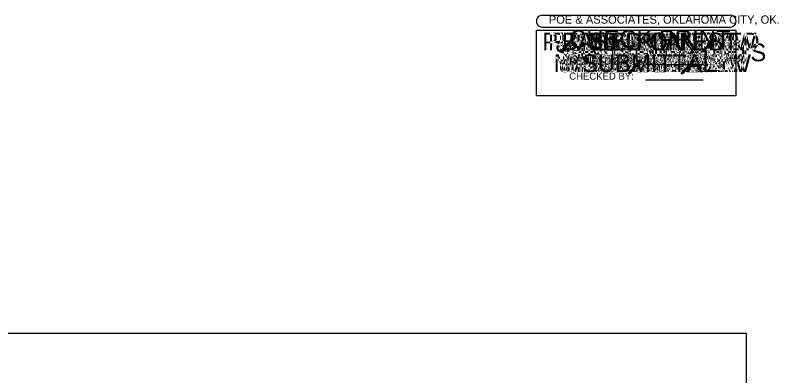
# Model space of a CAD drawing. Extents: x -98.3 to -54.8, y -26.7 to 2.7.
# Drawn here: x -74.57 to -61.71, y -3.42 to 2.66 of the extents above; entities that cross this region are included whole.
import ezdxf

# ---------------------------------------------------------------- set-up
doc = ezdxf.new("R2010")
doc.units = 0
for name, color, linetype in [('SHT_Plot_Shape_Full', 7, 'Continuous'), ('SHT_Stamp_30_Submit', 7, 'Continuous'), ('SHT_Stamp_60_Submit', 7, 'Continuous'), ('SHT_Stamp_70_Submit', 7, 'Continuous'), ('SHT_Stamp_Check_Print', 7, 'Continuous'), ('SHT_Stamp_Est_Inf', 7, 'Continuous'), ('SHT_Stamp_FFR', 7, 'Continuous'), ('SHT_Stamp_Info_Material', 7, 'Continuous'), ('SHT_Stamp_No_Const', 7, 'Continuous'), ('SHT_Stamp_No_Design', 7, 'Continuous'), ('SHT_Stamp_Plan_Hand', 7, 'Continuous'), ('SHT_Stamp_Pre_Plan', 7, 'Continuous'), ('SHT_Stamp_Prop_RW', 7, 'Continuous'), ('SHT_Stamp_Ret_Sub', 7, 'Continuous'), ('SHT_Stamp_Rev_Prop_RW', 7, 'Continuous'), ('SHT_Stamp_Rev_Sheet', 7, 'Continuous'), ('SHT_Stamp_RW_Utilities_Meeting', 7, 'Continuous'), ('SHT_Stamp_RW_Utilities_Review', 7, 'Continuous'), ('SHT_Stamp_Send_Comments', 7, 'Continuous')]:
    doc.layers.add(name, color=color, linetype=linetype)

msp = doc.modelspace()

# ---------------------------------------------------------------- linework, layer by layer
at = {"layer": 'SHT_Plot_Shape_Full'}
msp.add_lwpolyline([(-98.262, -2.701), (-62.262, -2.701), (-62.262, -26.701), (-98.262, -26.701)], close=True, dxfattribs=at)
at = {"layer": 'SHT_Stamp_30_Submit'}
for p, q in [((-65.696, 2.658), (-62.53, 2.658)), ((-65.696, 2.458), (-62.53, 2.458)), ((-65.796, 2.408), (-62.43, 2.408)), ((-65.796, 1.309), (-65.796, 2.408)), ((-62.43, 1.309), (-62.43, 2.408)), ((-64.553, 2.07), (-64.398, 2.243)), ((-64.535, 2.07), (-64.38, 2.243)), ((-64.53, 2.07), (-64.375, 2.243)), ((-64.522, 2.07), (-64.367, 2.243)), ((-64.398, 2.243), (-64.367, 2.243)), ((-64.553, 2.07), (-64.522, 2.07)), ((-65.796, 1.309), (-62.43, 1.309))]:
    msp.add_line(p, q, dxfattribs=at)
for centre, start, end in [((-65.696, 2.559), 89.9952, 270), ((-62.53, 2.559), 270, 90.0048)]:
    msp.add_arc(centre, 0.1, start, end, dxfattribs=at)
at = {"layer": 'SHT_Stamp_60_Submit'}
for p, q in [((-65.696, 2.658), (-62.53, 2.658)), ((-65.696, 2.458), (-62.53, 2.458)), ((-65.796, 2.408), (-62.43, 2.408)), ((-65.796, 1.309), (-65.796, 2.408)), ((-62.43, 1.309), (-62.43, 2.408)), ((-64.553, 2.07), (-64.398, 2.243)), ((-64.535, 2.07), (-64.38, 2.243)), ((-64.53, 2.07), (-64.375, 2.243)), ((-64.522, 2.07), (-64.367, 2.243)), ((-64.398, 2.243), (-64.367, 2.243)), ((-64.553, 2.07), (-64.522, 2.07)), ((-65.796, 1.309), (-62.43, 1.309))]:
    msp.add_line(p, q, dxfattribs=at)
for centre, start, end in [((-65.696, 2.559), 89.9952, 270), ((-62.53, 2.559), 270, 90.0048)]:
    msp.add_arc(centre, 0.1, start, end, dxfattribs=at)
at = {"layer": 'SHT_Stamp_70_Submit'}
for p, q in [((-65.696, 2.658), (-62.53, 2.658)), ((-65.696, 2.458), (-62.53, 2.458)), ((-65.796, 2.408), (-62.43, 2.408)), ((-65.796, 1.309), (-65.796, 2.408)), ((-62.43, 1.309), (-62.43, 2.408)), ((-64.553, 2.07), (-64.398, 2.243)), ((-64.535, 2.07), (-64.38, 2.243)), ((-64.53, 2.07), (-64.375, 2.243)), ((-64.522, 2.07), (-64.367, 2.243)), ((-64.398, 2.243), (-64.367, 2.243)), ((-64.553, 2.07), (-64.522, 2.07)), ((-65.796, 1.309), (-62.43, 1.309))]:
    msp.add_line(p, q, dxfattribs=at)
for centre, start, end in [((-65.696, 2.559), 89.9952, 270), ((-62.53, 2.559), 270, 90.0048)]:
    msp.add_arc(centre, 0.1, start, end, dxfattribs=at)
at = {"layer": 'SHT_Stamp_Check_Print'}
for p, q in [((-65.696, 2.658), (-62.53, 2.658)), ((-65.696, 2.458), (-62.53, 2.458)), ((-65.796, 2.408), (-62.43, 2.408)), ((-65.796, 1.309), (-65.796, 2.408)), ((-62.43, 1.309), (-62.43, 2.408)), ((-63.955, 1.827), (-62.984, 1.827)), ((-63.955, 1.571), (-62.984, 1.571)), ((-65.796, 1.309), (-62.43, 1.309))]:
    msp.add_line(p, q, dxfattribs=at)
for centre, start, end in [((-65.696, 2.559), 89.9952, 270), ((-62.53, 2.559), 270, 90.0048)]:
    msp.add_arc(centre, 0.1, start, end, dxfattribs=at)
at = {"layer": 'SHT_Stamp_Est_Inf'}
for p, q in [((-65.696, 2.658), (-62.53, 2.658)), ((-65.696, 2.458), (-62.53, 2.458)), ((-65.796, 2.408), (-62.43, 2.408)), ((-65.796, 1.309), (-65.796, 2.408)), ((-62.43, 1.309), (-62.43, 2.408)), ((-65.796, 1.309), (-62.43, 1.309))]:
    msp.add_line(p, q, dxfattribs=at)
for centre, start, end in [((-65.696, 2.559), 89.9952, 270), ((-62.53, 2.559), 270, 90.0048)]:
    msp.add_arc(centre, 0.1, start, end, dxfattribs=at)
at = {"layer": 'SHT_Stamp_FFR'}
for p, q in [((-65.696, 2.658), (-62.53, 2.658)), ((-65.696, 2.458), (-62.53, 2.458)), ((-65.796, 2.408), (-62.43, 2.408)), ((-65.796, 1.309), (-65.796, 2.408)), ((-62.43, 1.309), (-62.43, 2.408)), ((-65.796, 1.309), (-62.43, 1.309))]:
    msp.add_line(p, q, dxfattribs=at)
for centre, start, end in [((-65.696, 2.559), 89.9952, 270), ((-62.53, 2.559), 270, 90.0048)]:
    msp.add_arc(centre, 0.1, start, end, dxfattribs=at)
at = {"layer": 'SHT_Stamp_Info_Material'}
for p, q in [((-65.696, 2.658), (-62.53, 2.658)), ((-65.696, 2.458), (-62.53, 2.458)), ((-65.796, 2.408), (-62.43, 2.408)), ((-65.796, 1.309), (-65.796, 2.408)), ((-62.43, 1.309), (-62.43, 2.408)), ((-65.796, 1.309), (-62.43, 1.309))]:
    msp.add_line(p, q, dxfattribs=at)
for centre, start, end in [((-65.696, 2.559), 89.9952, 270), ((-62.53, 2.559), 270, 90.0048)]:
    msp.add_arc(centre, 0.1, start, end, dxfattribs=at)
at = {"layer": 'SHT_Stamp_No_Const'}
for p, q in [((-65.696, 2.658), (-62.53, 2.658)), ((-65.696, 2.458), (-62.53, 2.458)), ((-65.796, 2.408), (-62.43, 2.408)), ((-65.796, 1.309), (-65.796, 2.408)), ((-62.43, 1.309), (-62.43, 2.408)), ((-65.796, 1.309), (-62.43, 1.309))]:
    msp.add_line(p, q, dxfattribs=at)
for centre, start, end in [((-65.696, 2.559), 89.9952, 270), ((-62.53, 2.559), 270, 90.0048)]:
    msp.add_arc(centre, 0.1, start, end, dxfattribs=at)
at = {"layer": 'SHT_Stamp_No_Design'}
for p, q in [((-65.696, 2.658), (-62.53, 2.658)), ((-65.696, 2.458), (-62.53, 2.458)), ((-65.796, 2.408), (-62.43, 2.408)), ((-65.796, 1.309), (-65.796, 2.408)), ((-62.43, 1.309), (-62.43, 2.408)), ((-65.796, 1.309), (-62.43, 1.309))]:
    msp.add_line(p, q, dxfattribs=at)
for centre, start, end in [((-65.696, 2.559), 89.9952, 270), ((-62.53, 2.559), 270, 90.0048)]:
    msp.add_arc(centre, 0.1, start, end, dxfattribs=at)
at = {"layer": 'SHT_Stamp_Plan_Hand'}
for p, q in [((-65.696, 2.658), (-62.53, 2.658)), ((-65.696, 2.458), (-62.53, 2.458)), ((-65.796, 2.408), (-62.43, 2.408)), ((-65.796, 1.309), (-65.796, 2.408)), ((-62.43, 1.309), (-62.43, 2.408)), ((-65.796, 1.309), (-62.43, 1.309))]:
    msp.add_line(p, q, dxfattribs=at)
for centre, start, end in [((-65.696, 2.559), 89.9952, 270), ((-62.53, 2.559), 270, 90.0048)]:
    msp.add_arc(centre, 0.1, start, end, dxfattribs=at)
at = {"layer": 'SHT_Stamp_Pre_Plan'}
for p, q in [((-65.696, 2.658), (-62.53, 2.658)), ((-65.696, 2.458), (-62.53, 2.458)), ((-65.796, 2.408), (-62.43, 2.408)), ((-65.796, 1.309), (-65.796, 2.408)), ((-62.43, 1.309), (-62.43, 2.408)), ((-65.796, 1.309), (-62.43, 1.309))]:
    msp.add_line(p, q, dxfattribs=at)
for centre, start, end in [((-65.696, 2.559), 89.9952, 270), ((-62.53, 2.559), 270, 90.0048)]:
    msp.add_arc(centre, 0.1, start, end, dxfattribs=at)
at = {"layer": 'SHT_Stamp_Prop_RW'}
for p, q in [((-65.696, 2.658), (-62.53, 2.658)), ((-65.696, 2.458), (-62.53, 2.458)), ((-65.796, 2.408), (-62.43, 2.408)), ((-65.796, 1.309), (-65.796, 2.408)), ((-62.43, 1.309), (-62.43, 2.408)), ((-64.249, 1.681), (-64.057, 1.894)), ((-64.227, 1.681), (-64.035, 1.894)), ((-64.221, 1.681), (-64.029, 1.894)), ((-64.212, 1.681), (-64.02, 1.894)), ((-64.057, 1.894), (-64.02, 1.894)), ((-64.249, 1.681), (-64.212, 1.681)), ((-65.796, 1.309), (-62.43, 1.309))]:
    msp.add_line(p, q, dxfattribs=at)
for centre, start, end in [((-65.696, 2.559), 89.9952, 270), ((-62.53, 2.559), 270, 90.0048)]:
    msp.add_arc(centre, 0.1, start, end, dxfattribs=at)
at = {"layer": 'SHT_Stamp_Ret_Sub'}
for p, q in [((-65.696, 2.658), (-62.53, 2.658)), ((-65.696, 2.458), (-62.53, 2.458)), ((-65.796, 2.408), (-62.43, 2.408)), ((-65.796, 1.309), (-65.796, 2.408)), ((-62.43, 1.309), (-62.43, 2.408)), ((-65.796, 1.309), (-62.43, 1.309))]:
    msp.add_line(p, q, dxfattribs=at)
for centre, start, end in [((-65.696, 2.559), 89.9952, 270), ((-62.53, 2.559), 270, 90.0048)]:
    msp.add_arc(centre, 0.1, start, end, dxfattribs=at)
at = {"layer": 'SHT_Stamp_Rev_Prop_RW'}
for p, q in [((-65.696, 2.658), (-62.53, 2.658)), ((-65.696, 2.458), (-62.53, 2.458)), ((-65.796, 2.408), (-62.43, 2.408)), ((-65.796, 1.309), (-65.796, 2.408)), ((-62.43, 1.309), (-62.43, 2.408)), ((-63.359, 1.678), (-63.167, 1.891)), ((-63.337, 1.678), (-63.145, 1.891)), ((-63.331, 1.678), (-63.139, 1.891)), ((-63.321, 1.678), (-63.129, 1.891)), ((-63.167, 1.891), (-63.129, 1.891)), ((-63.359, 1.678), (-63.321, 1.678)), ((-65.796, 1.309), (-62.43, 1.309))]:
    msp.add_line(p, q, dxfattribs=at)
for centre, start, end in [((-65.696, 2.559), 89.9952, 270), ((-62.53, 2.559), 270, 90.0048)]:
    msp.add_arc(centre, 0.1, start, end, dxfattribs=at)
at = {"layer": 'SHT_Stamp_Rev_Sheet'}
for p, q in [((-65.696, 2.658), (-62.53, 2.658)), ((-65.696, 2.458), (-62.53, 2.458)), ((-65.796, 2.408), (-62.43, 2.408)), ((-65.796, 1.309), (-65.796, 2.408)), ((-62.43, 1.309), (-62.43, 2.408)), ((-65.796, 1.309), (-62.43, 1.309))]:
    msp.add_line(p, q, dxfattribs=at)
for centre, start, end in [((-65.696, 2.559), 89.9952, 270), ((-62.53, 2.559), 270, 90.0048)]:
    msp.add_arc(centre, 0.1, start, end, dxfattribs=at)
at = {"layer": 'SHT_Stamp_RW_Utilities_Meeting'}
for p, q in [((-65.696, 2.658), (-62.53, 2.658)), ((-65.696, 2.458), (-62.53, 2.458)), ((-65.796, 2.408), (-62.43, 2.408)), ((-65.796, 1.309), (-65.796, 2.408)), ((-62.43, 1.309), (-62.43, 2.408)), ((-65.394, 2.048), (-65.202, 2.261)), ((-65.372, 2.048), (-65.18, 2.261)), ((-65.366, 2.048), (-65.174, 2.261)), ((-65.356, 2.048), (-65.164, 2.261)), ((-65.202, 2.261), (-65.164, 2.261)), ((-65.394, 2.048), (-65.356, 2.048)), ((-65.796, 1.309), (-62.43, 1.309))]:
    msp.add_line(p, q, dxfattribs=at)
for centre, start, end in [((-65.696, 2.559), 89.9952, 270), ((-62.53, 2.559), 270, 90.0048)]:
    msp.add_arc(centre, 0.1, start, end, dxfattribs=at)
at = {"layer": 'SHT_Stamp_RW_Utilities_Review'}
for p, q in [((-65.696, 2.658), (-62.53, 2.658)), ((-65.696, 2.458), (-62.53, 2.458)), ((-65.796, 2.408), (-62.43, 2.408)), ((-65.796, 1.309), (-65.796, 2.408)), ((-62.43, 1.309), (-62.43, 2.408)), ((-63.006, 2.048), (-62.814, 2.261)), ((-62.984, 2.048), (-62.792, 2.261)), ((-62.977, 2.048), (-62.785, 2.261)), ((-62.968, 2.048), (-62.776, 2.261)), ((-62.814, 2.261), (-62.776, 2.261)), ((-63.006, 2.048), (-62.968, 2.048)), ((-65.796, 1.309), (-62.43, 1.309))]:
    msp.add_line(p, q, dxfattribs=at)
for centre, start, end in [((-65.696, 2.559), 89.9952, 270), ((-62.53, 2.559), 270, 90.0048)]:
    msp.add_arc(centre, 0.1, start, end, dxfattribs=at)
at = {"layer": 'SHT_Stamp_Send_Comments'}
for p, q in [((-65.696, 2.658), (-62.53, 2.658)), ((-65.696, 2.458), (-62.53, 2.458)), ((-65.796, 2.408), (-62.43, 2.408)), ((-65.796, 1.309), (-65.796, 2.408)), ((-62.43, 1.309), (-62.43, 2.408)), ((-65.796, 1.309), (-62.43, 1.309))]:
    msp.add_line(p, q, dxfattribs=at)
for centre, start, end in [((-65.696, 2.559), 89.9952, 270), ((-62.53, 2.559), 270, 90.0048)]:
    msp.add_arc(centre, 0.1, start, end, dxfattribs=at)

# ---------------------------------------------------------------- texts
at = {"layer": 'SHT_Stamp_30_Submit'}
for s, height, p in [('POE & ASSOCIATES, OKLAHOMA CITY, OK.', 0.14, (-65.586, 2.516)), ('30   PLAN', 0.3, (-64.894, 2.066)), ('O', 0.153, (-64.587, 2.155)), ('O', 0.153, (-64.436, 2.071)), ('SUBMITTAL', 0.3, (-65.025, 1.7))]:
    msp.add_text(s, height=height, dxfattribs=at).set_placement(p)
at = {"layer": 'SHT_Stamp_60_Submit'}
for s, height, p in [('POE & ASSOCIATES, OKLAHOMA CITY, OK.', 0.14, (-65.586, 2.516)), ('60   PLAN', 0.3, (-64.901, 2.066)), ('O', 0.153, (-64.587, 2.155)), ('O', 0.153, (-64.436, 2.071)), ('SUBMITTAL', 0.3, (-65.025, 1.7))]:
    msp.add_text(s, height=height, dxfattribs=at).set_placement(p)
at = {"layer": 'SHT_Stamp_70_Submit'}
for s, height, p in [('POE & ASSOCIATES, OKLAHOMA CITY, OK.', 0.14, (-65.586, 2.516)), ('70   PLAN', 0.3, (-64.901, 2.066)), ('O', 0.153, (-64.587, 2.155)), ('O', 0.153, (-64.436, 2.071)), ('SUBMITTAL', 0.3, (-65.025, 1.7))]:
    msp.add_text(s, height=height, dxfattribs=at).set_placement(p)
at = {"layer": 'SHT_Stamp_Check_Print'}
for s, height, p in [('POE & ASSOCIATES, OKLAHOMA CITY, OK.', 0.14, (-65.586, 2.516)), ('CHECK PRINT', 0.3, (-65.244, 2.11)), ('REVISED BY:', 0.12, (-65.242, 1.827)), ('CHECKED BY:', 0.12, (-65.242, 1.572))]:
    msp.add_text(s, height=height, dxfattribs=at).set_placement(p)
at = {"layer": 'SHT_Stamp_Est_Inf'}
for s, height, p in [('POE & ASSOCIATES, OKLAHOMA CITY, OK.', 0.14, (-65.586, 2.516)), ('BASED ON EST.', 0.3, (-65.365, 2.066)), ('INFORMATION', 0.3, (-65.244, 1.7))]:
    msp.add_text(s, height=height, dxfattribs=at).set_placement(p)
at = {"layer": 'SHT_Stamp_FFR'}
for s, height, p in [('POE & ASSOCIATES, OKLAHOMA CITY, OK.', 0.14, (-65.586, 2.516)), ('FINAL FIELD', 0.3, (-65.144, 2.066)), ('REVIEW', 0.3, (-64.717, 1.7))]:
    msp.add_text(s, height=height, dxfattribs=at).set_placement(p)
at = {"layer": 'SHT_Stamp_Info_Material'}
for s, height, p in [('POE & ASSOCIATES, OKLAHOMA CITY, OK.', 0.14, (-65.586, 2.516)), ('INFORMATION', 0.3, (-65.244, 2.066)), ('MATERIAL ONLY', 0.3, (-65.502, 1.7))]:
    msp.add_text(s, height=height, dxfattribs=at).set_placement(p)
at = {"layer": 'SHT_Stamp_No_Const'}
for s, height, p in [('POE & ASSOCIATES, OKLAHOMA CITY, OK.', 0.14, (-65.586, 2.516)), ('NOT TO BE USED', 0.3, (-65.555, 2.066)), ('FOR CONST.', 0.3, (-65.065, 1.7))]:
    msp.add_text(s, height=height, dxfattribs=at).set_placement(p)
at = {"layer": 'SHT_Stamp_No_Design'}
for s, height, p in [('POE & ASSOCIATES, OKLAHOMA CITY, OK.', 0.14, (-65.586, 2.516)), ('NOT TO BE USED', 0.3, (-65.555, 2.066)), ('FOR DESIGN', 0.3, (-65.083, 1.7))]:
    msp.add_text(s, height=height, dxfattribs=at).set_placement(p)
at = {"layer": 'SHT_Stamp_Plan_Hand'}
for s, height, p in [('POE & ASSOCIATES, OKLAHOMA CITY, OK.', 0.14, (-65.586, 2.516)), ('PLAN-IN-HAND', 0.3, (-65.312, 1.883))]:
    msp.add_text(s, height=height, dxfattribs=at).set_placement(p)
at = {"layer": 'SHT_Stamp_Pre_Plan'}
for s, height, p in [('POE & ASSOCIATES, OKLAHOMA CITY, OK.', 0.14, (-65.586, 2.516)), ('PRELIMINARY', 0.3, (-65.228, 2.066)), ('PLANS', 0.3, (-64.621, 1.7))]:
    msp.add_text(s, height=height, dxfattribs=at).set_placement(p)
at = {"layer": 'SHT_Stamp_Prop_RW'}
for s, height, p in [('POE & ASSOCIATES, OKLAHOMA CITY, OK.', 0.14, (-65.586, 2.516)), ('PROPOSED', 0.3, (-64.887, 2.066)), ('R W', 0.3, (-64.455, 1.7))]:
    msp.add_text(s, height=height, dxfattribs=at).set_placement(p)
at = {"layer": 'SHT_Stamp_Ret_Sub'}
for s, height, p in [('POE & ASSOCIATES, OKLAHOMA CITY, OK.', 0.14, (-65.586, 2.516)), ('RET. SUBMITTED', 0.3, (-65.378, 2.066)), ('MATERIALS', 0.3, (-65.037, 1.7))]:
    msp.add_text(s, height=height, dxfattribs=at).set_placement(p)
at = {"layer": 'SHT_Stamp_Rev_Prop_RW'}
for s, height, p in [('POE & ASSOCIATES, OKLAHOMA CITY, OK.', 0.14, (-65.586, 2.516)), ('REVISED', 0.3, (-64.759, 2.066)), ('PROPOSED R W', 0.3, (-65.345, 1.7))]:
    msp.add_text(s, height=height, dxfattribs=at).set_placement(p)
at = {"layer": 'SHT_Stamp_Rev_Sheet'}
for s, height, p in [('POE & ASSOCIATES, OKLAHOMA CITY, OK.', 0.14, (-65.586, 2.516)), ('REVISED SHEET', 0.3, (-65.362, 1.883))]:
    msp.add_text(s, height=height, dxfattribs=at).set_placement(p)
at = {"layer": 'SHT_Stamp_RW_Utilities_Meeting'}
for s, height, p in [('POE & ASSOCIATES, OKLAHOMA CITY, OK.', 0.14, (-65.586, 2.516)), ('R W & UTILITIES', 0.3, (-65.601, 2.066)), ('MEETING', 0.3, (-64.833, 1.7))]:
    msp.add_text(s, height=height, dxfattribs=at).set_placement(p)
at = {"layer": 'SHT_Stamp_RW_Utilities_Review'}
for s, height, p in [('POE & ASSOCIATES, OKLAHOMA CITY, OK.', 0.14, (-65.586, 2.516)), ('PRELIMINARY R W', 0.3, (-65.697, 2.066)), ('& UTIL.  REVIEW', 0.3, (-65.414, 1.7))]:
    msp.add_text(s, height=height, dxfattribs=at).set_placement(p)
at = {"layer": 'SHT_Stamp_Send_Comments'}
for s, height, p in [('POE & ASSOCIATES, OKLAHOMA CITY, OK.', 0.14, (-65.586, 2.516)), ('SEND COMMENTS', 0.3, (-65.49, 1.883))]:
    msp.add_text(s, height=height, dxfattribs=at).set_placement(p)

doc.saveas('drawing.dxf')
